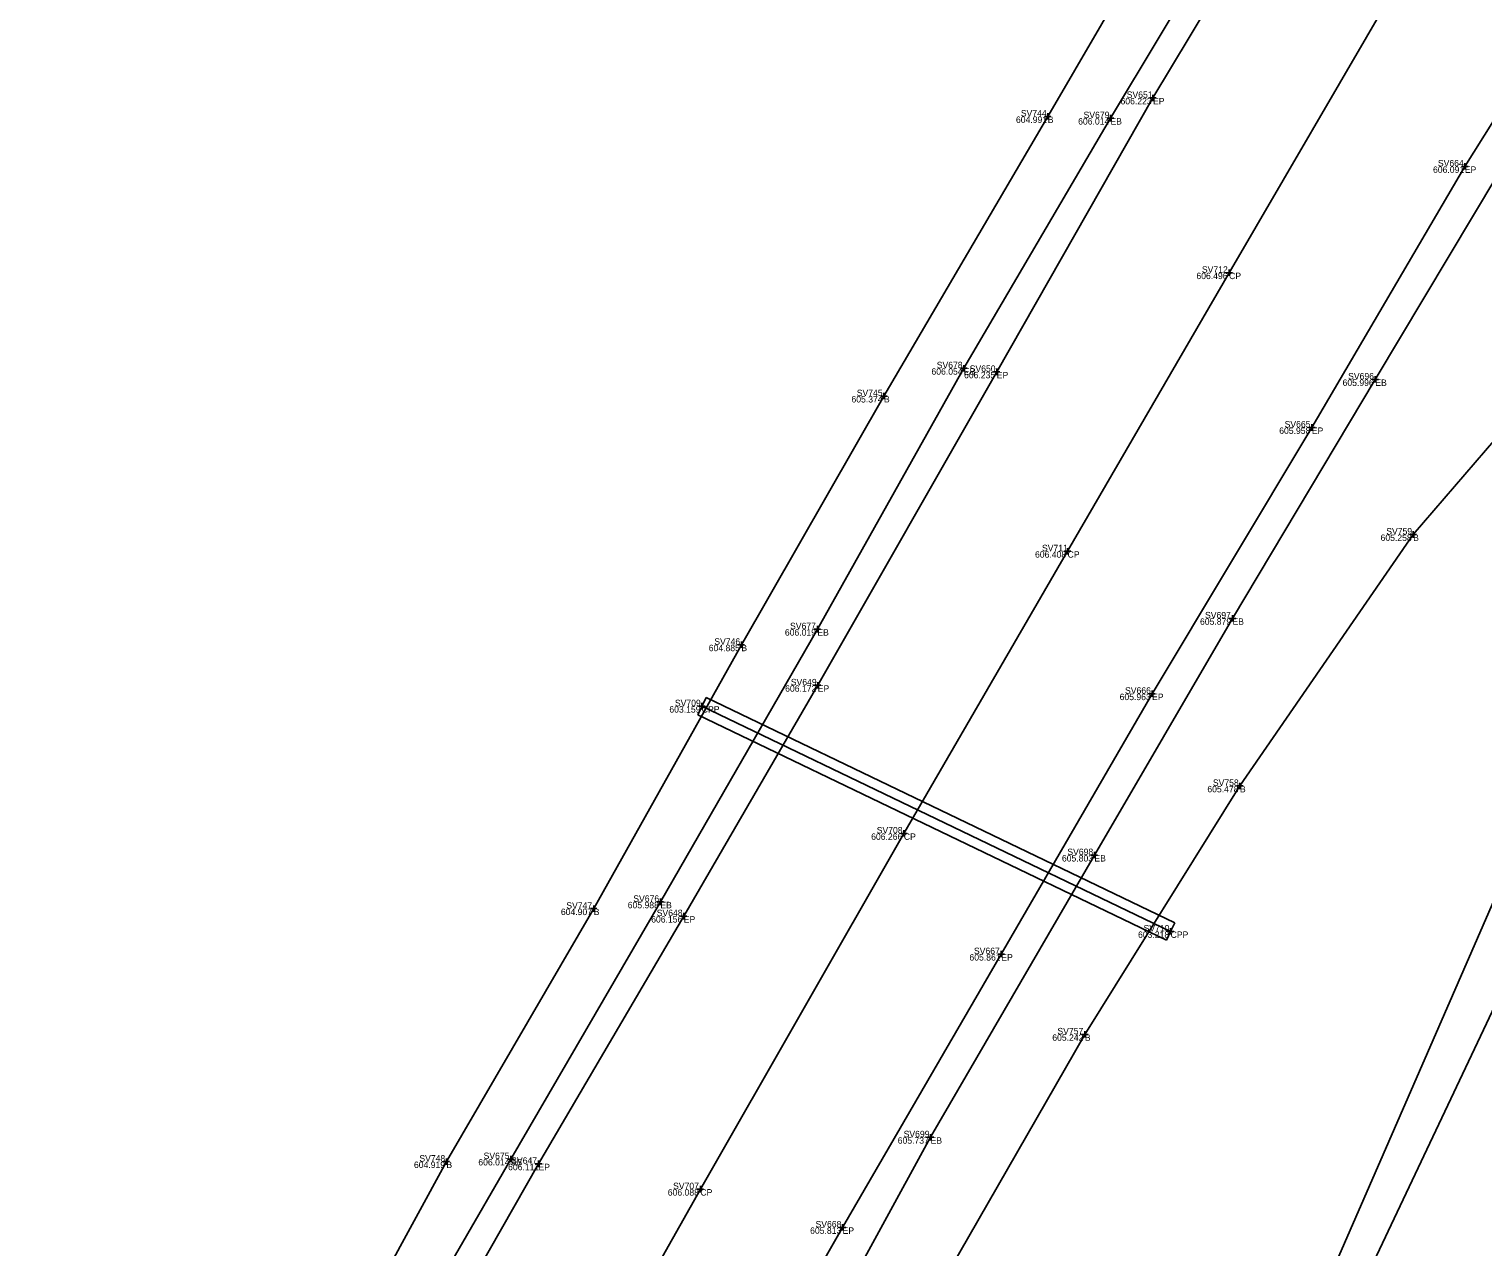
# Model space of a CAD drawing. Extents: x -2 to 1979875, y -2 to 232027.
# Drawn here: x 1978861.3 to 1978974.2, y 231836.1 to 231930.6 of the extents above; entities that cross this region are included whole.
import ezdxf

# ---------------------------------------------------------------- set-up
doc = ezdxf.new("R2010")
doc.units = 0
for name, color, linetype in [('_CIVIL_CONSTRUCTION', 7, 'Continuous'), ('DR_X_Storm_Sewer', 7, 'Continuous'), ('GE_P_Alignment', 7, 'Continuous'), ('GE_X_Alignment', 7, 'Continuous'), ('GE_X_Alignment_1000_Curve_Data', 7, 'Continuous'), ('GE_X_Alignment_1000_Stations', 7, 'Continuous'), ('GE_X_Alignment_100_Curve_Data', 7, 'Continuous'), ('GE_X_Alignment_100_Stations', 7, 'Continuous'), ('SC_Scratch1', 7, 'Continuous'), ('UT_X_Overhead_Cable_TV', 7, 'Continuous'), ('UT_X_Overhead_Electric', 7, 'Continuous')]:
    doc.layers.add(name, color=color, linetype=linetype)

msp = doc.modelspace()

# ---------------------------------------------------------------- linework, layer by layer
at = {"layer": 'DR_X_Storm_Sewer'}
for p, q in [((1978913.84, 231878.75), (1978913.19, 231877.4)), ((1978913.84, 231878.75), (1978950.24, 231861.26)), ((1978913.19, 231877.4), (1978949.59, 231859.91)), ((1978949.91, 231860.58), (1978950.24, 231861.26)), ((1978949.59, 231859.91), (1978949.91, 231860.58))]:
    msp.add_line(p, q, dxfattribs=at)
msp.add_lwpolyline([(1978913.51, 231878.07), (1978949.91, 231860.58)], dxfattribs=at)
at = {"layer": 'GE_P_Alignment'}
for points in [[(1978895.14, 231765.35), (1978907.41, 231788.99), (1978918.97, 231809.74), (1978931.23, 231831.66), (1978943.25, 231852.59), (1978955.29, 231871.88), (1978968.74, 231891.4), (1978984.79, 231910.03), (1978998.32, 231927.81), (1979010.99, 231949.26), (1979019.95, 231972.9), (1979026.5, 231993.68), (1979034.18, 232010.14)], [(1978950.81, 231976.44), (1978960.51, 231968.93), (1978960.22, 231962.28), (1978951.05, 231942.17), (1978940.37, 231923.86), (1978927.65, 231902.15), (1978916.58, 231882.84), (1978905.12, 231862.35), (1978893.68, 231842.71), (1978881.59, 231820.54), (1978870.08, 231799.88), (1978861.28, 231783.21)]]:
    msp.add_lwpolyline(points, dxfattribs=at)
at = {"layer": 'GE_X_Alignment_1000_Curve_Data'}
msp.add_lwpolyline([(1978877.19, 231774.62), (1978888.77, 231796.26), (1978900.69, 231818.02), (1978913.4, 231840.57), (1978929.2, 231868.19), (1978941.91, 231890.1), (1978954.45, 231911.73), (1978967.21, 231933.64), (1978980.41, 231956.12), (1978992.92, 231977.17), (1979005.51, 231998.49), (1979018.18, 232019.92)], dxfattribs=at)
at = {"layer": 'GE_X_Alignment_1000_Stations'}
for points in [[(1978866.56, 231780.35), (1978878.04, 231801.75), (1978889.24, 231822.17), (1978900.83, 231842.54), (1978912.11, 231861.77), (1978922.51, 231879.69), (1978936.41, 231904.03), (1978948.54, 231925.3), (1978961.72, 231947.25), (1978967.53, 231957.8), (1978968.97, 231965.69), (1978979.03, 231982.65), (1978989.75, 231999.88), (1978994.31, 232003.86), (1979007.45, 232025.2)], [(1979028.14, 232013.83), (1979017.28, 231995.62), (1979006.72, 231977.18), (1978996.23, 231957.96), (1978984.13, 231938.14), (1978972.75, 231919.98), (1978960.87, 231899.71), (1978948.47, 231879.04), (1978936.76, 231858.82), (1978924.44, 231837.6), (1978912.9, 231817.38), (1978899.1, 231792.35), (1978887.19, 231769.56)]]:
    msp.add_lwpolyline(points, dxfattribs=at)
at = {"layer": 'GE_X_Alignment_100_Curve_Data'}
for p, q in [((1978948.54, 231925.55), (1978948.54, 231925.05)), ((1978948.29, 231925.3), (1978948.79, 231925.3)), ((1978948.54, 231925.3), (1978948.54, 231925.3)), ((1978940.12, 231923.86), (1978940.62, 231923.86)), ((1978940.37, 231924.11), (1978940.37, 231923.61)), ((1978940.37, 231923.86), (1978940.37, 231923.86)), ((1978944.99, 231923.73), (1978945.49, 231923.73)), ((1978945.24, 231923.98), (1978945.24, 231923.48)), ((1978945.24, 231923.73), (1978945.24, 231923.73)), ((1978972.5, 231919.98), (1978973, 231919.98)), ((1978972.75, 231920.23), (1978972.75, 231919.73)), ((1978972.75, 231919.98), (1978972.75, 231919.98)), ((1978954.45, 231911.98), (1978954.45, 231911.48)), ((1978954.2, 231911.73), (1978954.7, 231911.73)), ((1978954.45, 231911.73), (1978954.45, 231911.73)), ((1978933.6, 231904.31), (1978934.1, 231904.31)), ((1978933.85, 231904.56), (1978933.85, 231904.06)), ((1978933.85, 231904.31), (1978933.85, 231904.31)), ((1978936.41, 231904.28), (1978936.41, 231903.78)), ((1978936.16, 231904.03), (1978936.66, 231904.03)), ((1978936.41, 231904.03), (1978936.41, 231904.03)), ((1978965.55, 231903.44), (1978966.05, 231903.44)), ((1978965.8, 231903.69), (1978965.8, 231903.19)), ((1978965.8, 231903.44), (1978965.8, 231903.44)), ((1978927.4, 231902.15), (1978927.9, 231902.15)), ((1978927.65, 231902.4), (1978927.65, 231901.9)), ((1978927.65, 231902.15), (1978927.65, 231902.15)), ((1978960.62, 231899.71), (1978961.12, 231899.71)), ((1978960.87, 231899.96), (1978960.87, 231899.46)), ((1978960.87, 231899.71), (1978960.87, 231899.71)), ((1978968.74, 231891.65), (1978968.74, 231891.15)), ((1978968.49, 231891.4), (1978968.99, 231891.4)), ((1978968.74, 231891.4), (1978968.74, 231891.4)), ((1978941.66, 231890.1), (1978942.16, 231890.1)), ((1978941.91, 231890.35), (1978941.91, 231889.85)), ((1978941.91, 231890.1), (1978941.91, 231890.1)), ((1978954.46, 231884.89), (1978954.96, 231884.89)), ((1978954.71, 231885.14), (1978954.71, 231884.64)), ((1978954.71, 231884.89), (1978954.71, 231884.89)), ((1978922.23, 231884.05), (1978922.73, 231884.05)), ((1978922.48, 231884.3), (1978922.48, 231883.8)), ((1978922.48, 231884.05), (1978922.48, 231884.05)), ((1978916.33, 231882.84), (1978916.83, 231882.84)), ((1978916.58, 231883.09), (1978916.58, 231882.59)), ((1978916.58, 231882.84), (1978916.58, 231882.84)), ((1978922.26, 231879.69), (1978922.76, 231879.69)), ((1978922.51, 231879.94), (1978922.51, 231879.44)), ((1978922.51, 231879.69), (1978922.51, 231879.69)), ((1978948.47, 231879.29), (1978948.47, 231878.79)), ((1978913.51, 231878.32), (1978913.51, 231877.82)), ((1978948.22, 231879.04), (1978948.72, 231879.04)), ((1978948.47, 231879.04), (1978948.47, 231879.04)), ((1978913.26, 231878.07), (1978913.76, 231878.07)), ((1978913.51, 231878.07), (1978913.51, 231878.07)), ((1978955.04, 231871.88), (1978955.54, 231871.88)), ((1978955.29, 231872.13), (1978955.29, 231871.63)), ((1978955.29, 231871.88), (1978955.29, 231871.88)), ((1978928.95, 231868.19), (1978929.45, 231868.19)), ((1978929.2, 231868.44), (1978929.2, 231867.94)), ((1978929.2, 231868.19), (1978929.2, 231868.19)), ((1978943.74, 231866.51), (1978944.24, 231866.51)), ((1978943.99, 231866.76), (1978943.99, 231866.26)), ((1978943.99, 231866.51), (1978943.99, 231866.51)), ((1978904.87, 231862.35), (1978905.37, 231862.35)), ((1978905.12, 231862.6), (1978905.12, 231862.1)), ((1978905.12, 231862.35), (1978905.12, 231862.35)), ((1978910.04, 231862.88), (1978910.54, 231862.88)), ((1978910.29, 231863.13), (1978910.29, 231862.63)), ((1978910.29, 231862.88), (1978910.29, 231862.88)), ((1978911.86, 231861.77), (1978912.36, 231861.77)), ((1978912.11, 231862.02), (1978912.11, 231861.52)), ((1978912.11, 231861.77), (1978912.11, 231861.77)), ((1978949.66, 231860.58), (1978950.16, 231860.58)), ((1978949.91, 231860.83), (1978949.91, 231860.33)), ((1978949.91, 231860.58), (1978949.91, 231860.58)), ((1978936.76, 231859.07), (1978936.76, 231858.57)), ((1978936.51, 231858.82), (1978937.01, 231858.82)), ((1978936.76, 231858.82), (1978936.76, 231858.82)), ((1978943, 231852.59), (1978943.5, 231852.59)), ((1978943.25, 231852.84), (1978943.25, 231852.34)), ((1978943.25, 231852.59), (1978943.25, 231852.59)), ((1978931.02, 231844.6), (1978931.52, 231844.6)), ((1978931.27, 231844.85), (1978931.27, 231844.35)), ((1978931.27, 231844.6), (1978931.27, 231844.6)), ((1978898.68, 231843.16), (1978898.68, 231842.66)), ((1978893.43, 231842.71), (1978893.93, 231842.71)), ((1978893.68, 231842.96), (1978893.68, 231842.46)), ((1978893.68, 231842.71), (1978893.68, 231842.71)), ((1978898.43, 231842.91), (1978898.93, 231842.91)), ((1978898.68, 231842.91), (1978898.68, 231842.91)), ((1978900.58, 231842.54), (1978901.08, 231842.54)), ((1978900.83, 231842.79), (1978900.83, 231842.29)), ((1978900.83, 231842.54), (1978900.83, 231842.54)), ((1978913.15, 231840.57), (1978913.65, 231840.57)), ((1978913.4, 231840.82), (1978913.4, 231840.32)), ((1978913.4, 231840.57), (1978913.4, 231840.57)), ((1978924.19, 231837.6), (1978924.69, 231837.6)), ((1978924.44, 231837.85), (1978924.44, 231837.35)), ((1978924.44, 231837.6), (1978924.44, 231837.6))]:
    msp.add_line(p, q, dxfattribs=at)
at = {"layer": 'SC_Scratch1'}
for points in [[(1979030.52, 232013.71), (1979018.47, 231994.12), (1979007.61, 231974.05), (1978997.37, 231956.52), (1978987.86, 231940.19), (1978977.2, 231922.5), (1978965.8, 231903.44), (1978954.71, 231884.89), (1978943.99, 231866.51), (1978931.27, 231844.6), (1978919.84, 231823.69), (1978908.2, 231803.52), (1978896.66, 231781.83), (1978889.46, 231768.29)], [(1978864.95, 231781.2), (1978875.33, 231801.36), (1978886.66, 231822.09), (1978898.68, 231842.91), (1978910.29, 231862.88), (1978922.48, 231884.05), (1978933.85, 231904.31), (1978945.24, 231923.73), (1978956.42, 231942.36), (1978966.77, 231961.66)]]:
    msp.add_lwpolyline(points, dxfattribs=at)
at = {"layer": 'UT_X_Overhead_Cable_TV'}
msp.add_lwpolyline([(1979041.07, 231994.22), (1978929, 231757.44), (1979009.41, 231399.95)], dxfattribs=at)
at = {"layer": 'UT_X_Overhead_Electric'}
msp.add_lwpolyline([(1978972.39, 232000.19), (1979025.8, 231979.51), (1978929, 231757.44), (1979009.41, 231399.95)], dxfattribs=at)

# ---------------------------------------------------------------- texts
at = {"layer": '_CIVIL_CONSTRUCTION'}
for s, p in [('606.223', (1978946.02, 231924.8)), ('604.991', (1978937.9, 231923.36)), ('606.014', (1978942.73, 231923.23)), ('606.091', (1978970.28, 231919.48)), ('606.496', (1978951.91, 231911.23)), ('606.054', (1978931.34, 231903.81)), ('606.235', (1978933.87, 231903.53)), ('605.996', (1978963.26, 231902.94)), ('605.374', (1978925.13, 231901.65)), ('605.958', (1978958.34, 231899.21)), ('605.258', (1978966.21, 231890.9)), ('606.408', (1978939.38, 231889.6)), ('605.879', (1978952.19, 231884.39)), ('606.019', (1978919.96, 231883.55)), ('604.885', (1978914.05, 231882.34)), ('606.172', (1978919.98, 231879.19)), ('605.963', (1978945.95, 231878.54)), ('603.159', (1978910.99, 231877.57)), ('605.478', (1978952.76, 231871.38)), ('606.266', (1978926.66, 231867.69)), ('605.803', (1978941.47, 231866.01)), ('604.907', (1978902.57, 231861.85)), ('605.988', (1978907.76, 231862.38)), ('606.156', (1978909.58, 231861.27)), ('603.218', (1978947.38, 231860.08)), ('605.861', (1978934.29, 231858.32)), ('605.242', (1978940.72, 231852.09)), ('605.737', (1978928.72, 231844.1)), ('604.919', (1978891.16, 231842.21)), ('606.014', (1978896.16, 231842.41)), ('606.111', (1978898.47, 231842.04)), ('606.088', (1978910.87, 231840.07)), ('605.813', (1978921.92, 231837.1))]:
    msp.add_text(s, height=0.5, dxfattribs=at).set_placement(p)
at = {"layer": 'GE_X_Alignment'}
for s, p in [('SV651', (1978946.5, 231925.3)), ('SV744', (1978938.28, 231923.86)), ('SV679', (1978943.15, 231923.73)), ('SV664', (1978970.66, 231919.98)), ('SV712', (1978952.34, 231911.73)), ('SV678', (1978931.75, 231904.31)), ('SV650', (1978934.31, 231904.03)), ('SV696', (1978963.69, 231903.44)), ('SV745', (1978925.54, 231902.15)), ('SV665', (1978958.76, 231899.71)), ('SV759', (1978966.65, 231891.4)), ('SV711', (1978939.92, 231890.1)), ('SV697', (1978952.58, 231884.89)), ('SV677', (1978920.36, 231884.05)), ('SV746', (1978914.48, 231882.84)), ('SV649', (1978920.42, 231879.69)), ('SV666', (1978946.37, 231879.04)), ('SV709', (1978911.42, 231878.07)), ('SV758', (1978953.19, 231871.88)), ('SV708', (1978927.09, 231868.19)), ('SV698', (1978941.89, 231866.51)), ('SV747', (1978902.99, 231862.35)), ('SV676', (1978908.19, 231862.88)), ('SV648', (1978910.01, 231861.77)), ('SV710', (1978947.81, 231860.58)), ('SV667', (1978934.64, 231858.82)), ('SV757', (1978941.12, 231852.59)), ('SV699', (1978929.18, 231844.6)), ('SV748', (1978891.58, 231842.71)), ('SV675', (1978896.57, 231842.91)), ('SV647', (1978898.71, 231842.54)), ('SV707', (1978911.28, 231840.57)), ('SV668', (1978922.34, 231837.6))]:
    msp.add_text(s, height=0.5, dxfattribs=at).set_placement(p)
at = {"layer": 'GE_X_Alignment_100_Stations'}
for s, p in [('EP', (1978948.54, 231924.8)), ('B', (1978940.37, 231923.36)), ('EB', (1978945.24, 231923.23)), ('EP', (1978972.75, 231919.48)), ('CP', (1978954.45, 231911.23)), ('EB', (1978933.85, 231903.81)), ('EP', (1978936.41, 231903.53)), ('EB', (1978965.8, 231902.94)), ('B', (1978927.65, 231901.65)), ('EP', (1978960.87, 231899.21)), ('B', (1978968.74, 231890.9)), ('CP', (1978941.91, 231889.6)), ('EB', (1978954.71, 231884.39)), ('EB', (1978922.48, 231883.55)), ('B', (1978916.58, 231882.34)), ('EP', (1978922.51, 231879.19)), ('EP', (1978948.47, 231878.54)), ('CPP', (1978913.51, 231877.57)), ('B', (1978955.29, 231871.38)), ('CP', (1978929.2, 231867.69)), ('EB', (1978943.99, 231866.01)), ('B', (1978905.12, 231861.85)), ('EB', (1978910.29, 231862.38)), ('EP', (1978912.11, 231861.27)), ('CPP', (1978949.91, 231860.08)), ('EP', (1978936.76, 231858.32)), ('B', (1978943.25, 231852.09)), ('EB', (1978931.27, 231844.1)), ('B', (1978893.68, 231842.21)), ('EB', (1978898.68, 231842.41)), ('EP', (1978900.83, 231842.04)), ('CP', (1978913.4, 231840.07)), ('EP', (1978924.44, 231837.1))]:
    msp.add_text(s, height=0.5, dxfattribs=at).set_placement(p)

doc.saveas('drawing.dxf')
